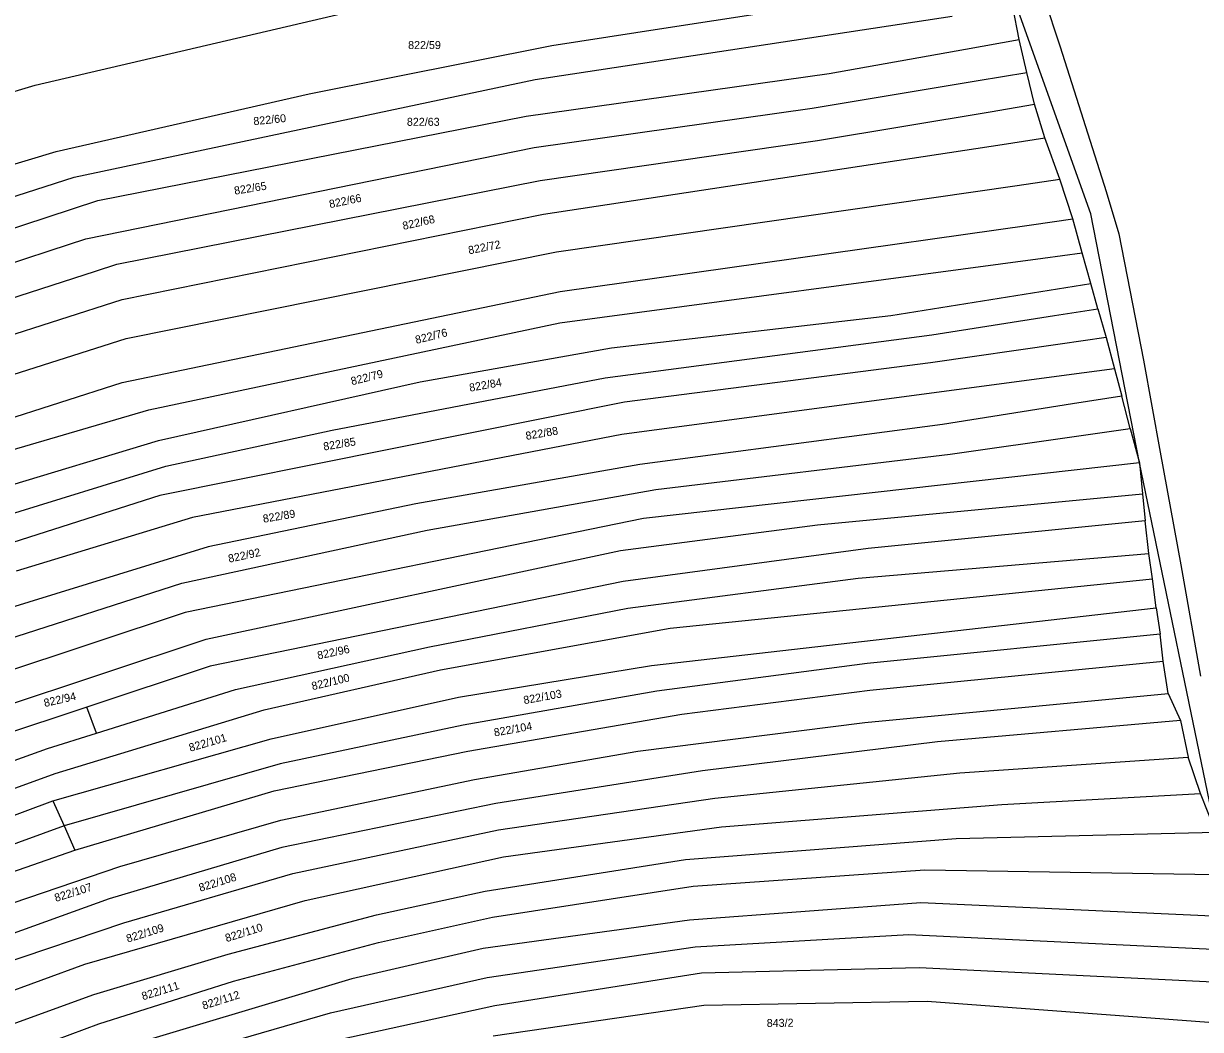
# Model space of a CAD drawing. Extents: x -580630 to -576196, y -1189024 to -1183567.
# Drawn here: x -577295.7 to -577045.8, y -1185235.3 to -1185021.8 of the extents above; entities that cross this region are included whole.
import ezdxf

# ---------------------------------------------------------------- set-up
doc = ezdxf.new("R2010")
doc.units = 0
for name, color, linetype in [('Vrstva 1', 7, 'Continuous'), ('Vrstva 13', 7, 'Continuous'), ('Vrstva 18', 7, 'Continuous'), ('Vrstva 4', 7, 'Continuous'), ('Vrstva 6', 7, 'Continuous')]:
    doc.layers.add(name, color=color, linetype=linetype)

msp = doc.modelspace()

# ---------------------------------------------------------------- linework, layer by layer
at = {"layer": 'Vrstva 1'}
for p, q in [((-577084.32, -1185025.19), (-577085.67, -1185018.29)), ((-577082.68, -1185032.21), (-577084.32, -1185025.19)), ((-577081.09, -1185038.95), (-577082.68, -1185032.21)), ((-577078.85, -1185046.08), (-577081.09, -1185038.95)), ((-577075.66, -1185054.87), (-577078.85, -1185046.08)), ((-577072.94, -1185063.28), (-577075.66, -1185054.87)), ((-577070.92, -1185070.47), (-577072.94, -1185063.28)), ((-577069.1, -1185077.02), (-577070.92, -1185070.47)), ((-577067.61, -1185082.36), (-577069.1, -1185077.02)), ((-577067.61, -1185082.36), (-577065.86, -1185088.46)), ((-577065.86, -1185088.46), (-577064.09, -1185095.09)), ((-577064.09, -1185095.09), (-577062.52, -1185100.91)), ((-577060.71, -1185107.79), (-577062.52, -1185100.91)), ((-577060.71, -1185107.79), (-577058.73, -1185115.05)), ((-577058.73, -1185115.05), (-577058.1, -1185121.64)), ((-577058.1, -1185121.64), (-577057.58, -1185127.39)), ((-577056.78, -1185134.27), (-577057.58, -1185127.39)), ((-577055.99, -1185139.68), (-577056.78, -1185134.27)), ((-577055.2, -1185145.82), (-577055.99, -1185139.68)), ((-577055.2, -1185145.82), (-577054.36, -1185151.44)), ((-577053.74, -1185157.16), (-577054.36, -1185151.44)), ((-577052.7, -1185164), (-577053.74, -1185157.16)), ((-577052.7, -1185164), (-577050.08, -1185169.78)), ((-577050.08, -1185169.78), (-577048.42, -1185177.5)), ((-577045.84, -1185185.23), (-577048.42, -1185177.5)), ((-577042.56, -1185193.47), (-577045.84, -1185185.23)), ((-577195.98, -1185236.67), (-577151.26, -1185230.19)), ((-577151.26, -1185230.19), (-577103.87, -1185229.35)), ((-577103.87, -1185229.35), (-577038.59, -1185234.2))]:
    msp.add_line(p, q, dxfattribs=at)
at = {"layer": 'Vrstva 13'}
for p, q in [((-577082.49, -1185005.84), (-577075.58, -1185026.74)), ((-577075.58, -1185026.74), (-577065.82, -1185057.49)), ((-577065.82, -1185057.49), (-577063.12, -1185066.43)), ((-577063.12, -1185066.43), (-577057.9, -1185093.25)), ((-577057.9, -1185093.25), (-577054.36, -1185112.81)), ((-577054.36, -1185112.81), (-577050, -1185136.71)), ((-577050, -1185136.71), (-577045.79, -1185160.34))]:
    msp.add_line(p, q, dxfattribs=at)
at = {"layer": 'Vrstva 4'}
for p, q in [((-577069.06, -1185062.23), (-577087.18, -1185011.6)), ((-577058.73, -1185115.05), (-577069.06, -1185062.23)), ((-577042.56, -1185193.47), (-577058.73, -1185115.05))]:
    msp.add_line(p, q, dxfattribs=at)
at = {"layer": 'Vrstva 6'}
for p, q in [((-577159.79, -1185022.79), (-577101.12, -1185013.75)), ((-577293.27, -1185034.92), (-577228.07, -1185019.66)), ((-577187.06, -1185033.66), (-577098.52, -1185020.24)), ((-577183.58, -1185026.45), (-577159.79, -1185022.79)), ((-577095.71, -1185027.23), (-577084.32, -1185025.19)), ((-577235.1, -1185036.72), (-577183.58, -1185026.45)), ((-577124.64, -1185032.42), (-577095.71, -1185027.23)), ((-577188.98, -1185041.47), (-577124.64, -1185032.42)), ((-577093.02, -1185033.92), (-577082.68, -1185032.21)), ((-577338.7, -1185048.57), (-577293.27, -1185034.92)), ((-577284.97, -1185054.4), (-577187.06, -1185033.66)), ((-577128.27, -1185039.77), (-577093.02, -1185033.92)), ((-577288.8, -1185048.97), (-577235.1, -1185036.72)), ((-577187.27, -1185048.1), (-577128.27, -1185039.77)), ((-577127.15, -1185046.66), (-577090.49, -1185040.52)), ((-577090.49, -1185040.52), (-577081.09, -1185038.95)), ((-577279.94, -1185059.37), (-577188.98, -1185041.47)), ((-577282.51, -1185067.48), (-577187.27, -1185048.1)), ((-577186.03, -1185055.1), (-577127.15, -1185046.66)), ((-577185.33, -1185062.28), (-577087.94, -1185047.46)), ((-577087.94, -1185047.46), (-577078.85, -1185046.08)), ((-577331.59, -1185061.88), (-577288.8, -1185048.97)), ((-577343.1, -1185073.16), (-577284.97, -1185054.4)), ((-577275.91, -1185072.89), (-577186.03, -1185055.1)), ((-577084.73, -1185056.18), (-577075.66, -1185054.87)), ((-577182.58, -1185070.27), (-577084.73, -1185056.18)), ((-577340.55, -1185079.35), (-577279.94, -1185059.37)), ((-577274.75, -1185080.39), (-577185.33, -1185062.28)), ((-577181.76, -1185078.7), (-577081.66, -1185064.52)), ((-577081.66, -1185064.52), (-577072.94, -1185063.28)), ((-577290.07, -1185069.97), (-577282.51, -1185067.48)), ((-577334.46, -1185084.57), (-577290.07, -1185069.97)), ((-577273.95, -1185088.68), (-577182.58, -1185070.27)), ((-577079.32, -1185071.6), (-577070.92, -1185070.47)), ((-577280.43, -1185074.35), (-577275.91, -1185072.89)), ((-577181.88, -1185085.37), (-577079.32, -1185071.6)), ((-577331.83, -1185090.94), (-577280.43, -1185074.35)), ((-577077.93, -1185078.42), (-577069.1, -1185077.02)), ((-577328.81, -1185097.67), (-577274.75, -1185080.39)), ((-577274.78, -1185098.03), (-577181.76, -1185078.7)), ((-577111.58, -1185083.76), (-577077.93, -1185078.42)), ((-577076.83, -1185083.8), (-577067.61, -1185082.36)), ((-577269.14, -1185103.8), (-577181.88, -1185085.37)), ((-577170.89, -1185090.65), (-577111.58, -1185083.76)), ((-577102.84, -1185087.87), (-577076.83, -1185083.8)), ((-577172.22, -1185097.02), (-577102.84, -1185087.87)), ((-577357.56, -1185115.27), (-577273.95, -1185088.68)), ((-577211.48, -1185097.85), (-577170.89, -1185090.65)), ((-577075.59, -1185089.86), (-577103.15, -1185093.84)), ((-577065.86, -1185088.46), (-577075.59, -1185089.86)), ((-577103.15, -1185093.84), (-577168.11, -1185102.16)), ((-577064.09, -1185095.09), (-577074.25, -1185096.45)), ((-577376.97, -1185130.66), (-577274.78, -1185098.03)), ((-577267.09, -1185110.29), (-577211.48, -1185097.85)), ((-577230.19, -1185108.13), (-577172.22, -1185097.02)), ((-577074.25, -1185096.45), (-577168.66, -1185109.06)), ((-577168.11, -1185102.16), (-577266.77, -1185122.01)), ((-577073.01, -1185102.56), (-577100.61, -1185106.89)), ((-577062.52, -1185100.91), (-577073.01, -1185102.56)), ((-577318.89, -1185118.41), (-577269.14, -1185103.8)), ((-577265.54, -1185115.74), (-577230.19, -1185108.13)), ((-577100.61, -1185106.89), (-577164.85, -1185115.43)), ((-577071.62, -1185109.34), (-577060.71, -1185107.79)), ((-577336.19, -1185131.23), (-577267.09, -1185110.29)), ((-577168.66, -1185109.06), (-577259.82, -1185126.65)), ((-577098.99, -1185113.23), (-577071.62, -1185109.34)), ((-577164.85, -1185115.43), (-577212.43, -1185123.76)), ((-577058.73, -1185115.05), (-577164.06, -1185126.85)), ((-577161.48, -1185120.73), (-577098.99, -1185113.23)), ((-577334.13, -1185136.99), (-577265.54, -1185115.74)), ((-577266.77, -1185122.01), (-577299.77, -1185132.51)), ((-577209.99, -1185129.38), (-577161.48, -1185120.73)), ((-577127.12, -1185128.22), (-577058.1, -1185121.64)), ((-577212.43, -1185123.76), (-577256.52, -1185132.91)), ((-577259.82, -1185126.65), (-577297.29, -1185138.06)), ((-577164.06, -1185126.85), (-577261.38, -1185146.81)), ((-577057.58, -1185127.39), (-577116.4, -1185133.22)), ((-577262.1, -1185140.59), (-577209.99, -1185129.38)), ((-577168.95, -1185133.68), (-577127.12, -1185128.22)), ((-577256.52, -1185132.91), (-577304.93, -1185147.83)), ((-577256.93, -1185152.49), (-577168.95, -1185133.68)), ((-577116.4, -1185133.22), (-577168.41, -1185140.21)), ((-577118.52, -1185139.54), (-577056.78, -1185134.27)), ((-577301.76, -1185153.33), (-577262.1, -1185140.59)), ((-577168.41, -1185140.21), (-577256.08, -1185158.21)), ((-577167.39, -1185145.88), (-577118.52, -1185139.54)), ((-577158.39, -1185150.13), (-577055.99, -1185139.68)), ((-577261.38, -1185146.81), (-577467.35, -1185215.3)), ((-577209.52, -1185154.11), (-577167.39, -1185145.88)), ((-577162.35, -1185158.1), (-577055.2, -1185145.82)), ((-577207.21, -1185158.98), (-577158.39, -1185150.13)), ((-577462.08, -1185220.46), (-577256.93, -1185152.49)), ((-577054.36, -1185151.44), (-577116.58, -1185157.62)), ((-577250.74, -1185163.16), (-577209.52, -1185154.11)), ((-577203.35, -1185164.79), (-577162.35, -1185158.1)), ((-577116.58, -1185157.62), (-577161.28, -1185163.51)), ((-577116.05, -1185163.34), (-577053.74, -1185157.16)), ((-577256.08, -1185158.21), (-577282.25, -1185166.89)), ((-577244.63, -1185167.47), (-577207.21, -1185158.98)), ((-577280.26, -1185172.45), (-577250.74, -1185163.16)), ((-577243.12, -1185173.64), (-577203.35, -1185164.79)), ((-577161.28, -1185163.51), (-577202.36, -1185170.76)), ((-577155.95, -1185168.41), (-577116.05, -1185163.34)), ((-577117.09, -1185170.19), (-577052.7, -1185164)), ((-577282.25, -1185166.89), (-577309.12, -1185175.8)), ((-577289.02, -1185180.98), (-577244.63, -1185167.47)), ((-577280.26, -1185172.45), (-577282.25, -1185166.89)), ((-577201.38, -1185176.25), (-577155.95, -1185168.41)), ((-577165.29, -1185176.26), (-577117.09, -1185170.19)), ((-577050.08, -1185169.78), (-577101.63, -1185174.26)), ((-577290.62, -1185175.71), (-577280.26, -1185172.45)), ((-577202.36, -1185170.76), (-577241.26, -1185178.98)), ((-577289.47, -1185186.78), (-577243.12, -1185173.64)), ((-577101.63, -1185174.26), (-577151.58, -1185180.43)), ((-577323.92, -1185187.64), (-577290.62, -1185175.71)), ((-577242.49, -1185184.68), (-577201.38, -1185176.25)), ((-577199.94, -1185182.3), (-577165.29, -1185176.26)), ((-577096.89, -1185180.89), (-577048.42, -1185177.5)), ((-577241.26, -1185178.98), (-577287.13, -1185192.09)), ((-577151.58, -1185180.43), (-577195.42, -1185187.37)), ((-577321.4, -1185192.81), (-577289.02, -1185180.98)), ((-577241.06, -1185190.93), (-577199.94, -1185182.3)), ((-577148.91, -1185186.24), (-577096.89, -1185180.89)), ((-577284.84, -1185197.24), (-577242.49, -1185184.68)), ((-577088, -1185187.6), (-577045.84, -1185185.23)), ((-577319.71, -1185198.12), (-577289.47, -1185186.78)), ((-577289.47, -1185186.78), (-577287.13, -1185192.09)), ((-577195.42, -1185187.37), (-577240.86, -1185196.72)), ((-577194.86, -1185192.93), (-577148.91, -1185186.24)), ((-577147.52, -1185192.34), (-577088, -1185187.6)), ((-577287.13, -1185192.09), (-577326.86, -1185206.56)), ((-577287.13, -1185192.09), (-577284.84, -1185197.24)), ((-577275.29, -1185200.71), (-577241.06, -1185190.93)), ((-577238.57, -1185202.19), (-577194.86, -1185192.93)), ((-577193.78, -1185198.71), (-577147.52, -1185192.34)), ((-577155.15, -1185199.27), (-577097.66, -1185194.81)), ((-577097.66, -1185194.81), (-577042.56, -1185193.47)), ((-577391.02, -1185234.57), (-577284.84, -1185197.24)), ((-577240.86, -1185196.72), (-577277.56, -1185207.63)), ((-577235.93, -1185207.96), (-577193.78, -1185198.71)), ((-577197.71, -1185205.95), (-577155.15, -1185199.27)), ((-577337.37, -1185221.89), (-577275.29, -1185200.71)), ((-577274.43, -1185212.67), (-577238.57, -1185202.19)), ((-577153.5, -1185204.93), (-577104.37, -1185201.43)), ((-577104.37, -1185201.43), (-577042.63, -1185202.46)), ((-577196.18, -1185211.51), (-577153.5, -1185204.93)), ((-577277.56, -1185207.63), (-577419.87, -1185258.8)), ((-577282.7, -1185221.44), (-577235.93, -1185207.96)), ((-577220.75, -1185211.02), (-577197.71, -1185205.95)), ((-577105.18, -1185208.46), (-577154.32, -1185212.16)), ((-577038.89, -1185211.45), (-577105.18, -1185208.46)), ((-577312.47, -1185225.54), (-577274.43, -1185212.67)), ((-577252.3, -1185219.35), (-577220.75, -1185211.02)), ((-577220.34, -1185216.88), (-577196.18, -1185211.51)), ((-577154.32, -1185212.16), (-577198.12, -1185218.12)), ((-577153.1, -1185217.81), (-577107.76, -1185215.14)), ((-577107.76, -1185215.14), (-577038.86, -1185218.5)), ((-577251.17, -1185225.11), (-577220.34, -1185216.88)), ((-577198.12, -1185218.12), (-577225.98, -1185224.6)), ((-577197.3, -1185224.29), (-577153.1, -1185217.81)), ((-577280.77, -1185227.94), (-577252.3, -1185219.35)), ((-577419.42, -1185271.54), (-577282.7, -1185221.44)), ((-577105.52, -1185222.28), (-577151.78, -1185223.41)), ((-577038.7, -1185225.51), (-577105.52, -1185222.28)), ((-577279.75, -1185234.14), (-577251.17, -1185225.11)), ((-577225.98, -1185224.6), (-577279.63, -1185240.65)), ((-577230.51, -1185231.8), (-577197.3, -1185224.29)), ((-577151.78, -1185223.41), (-577195.67, -1185230.3)), ((-577424.36, -1185279.88), (-577280.77, -1185227.94)), ((-577195.67, -1185230.3), (-577228.36, -1185237.49)), ((-577264.65, -1185241.65), (-577230.51, -1185231.8)), ((-577356.86, -1185262.65), (-577279.75, -1185234.14))]:
    msp.add_line(p, q, dxfattribs=at)

# ---------------------------------------------------------------- texts
at = {"layer": 'Vrstva 18'}
for s, p in [('822/59', (-577214.063, -1185027.22)), ('822/63', (-577214.324, -1185043.52))]:
    msp.add_text(s, height=1.7, dxfattribs=at).set_placement(p)
for s, rotation, p in [('822/60', 5.78688, (-577246.831, -1185043.396)), ('822/65', 9.05273, (-577250.869, -1185058.143)), ('822/66', 11.68834, (-577230.647, -1185061)), ('822/68', 12.83426, (-577215.039, -1185065.619)), ('822/72', 11.22997, (-577201.117, -1185070.803)), ('822/76', 13.92288, (-577212.321, -1185089.814)), ('822/79', 14.20935, (-577225.986, -1185098.595)), ('822/84', 10.14135, (-577200.926, -1185099.961)), ('822/88', 9.74028, (-577188.961, -1185110.195)), ('822/85', 9.39651, (-577231.922, -1185112.453)), ('822/89', 9.62569, (-577244.762, -1185127.783)), ('822/92', 12.14671, (-577252.072, -1185136.26)), ('822/96', 12.03211, (-577233.152, -1185156.796)), ('822/100', 13.46451, (-577234.342, -1185163.322)), ('822/94', 12.94885, (-577291.207, -1185166.893)), ('822/103', 10.37054, (-577189.404, -1185166.295)), ('822/104', 10.14135, (-577195.692, -1185173.151)), ('822/101', 16.272, (-577260.324, -1185176.389)), ('822/108', 17.36062, (-577258.201, -1185206.118)), ('822/107', 17.36062, (-577288.854, -1185208.26)), ('822/109', 17.36062, (-577273.602, -1185216.912)), ('822/110', 17.36062, (-577252.61, -1185216.808)), ('822/111', 17.36062, (-577270.342, -1185229.146)), ('822/112', 17.36062, (-577257.485, -1185231.122)), ('843/2', 0.74484, (-577137.9, -1185234.817))]:
    msp.add_text(s, height=1.7, rotation=rotation, dxfattribs=at).set_placement(p)

doc.saveas('drawing.dxf')
